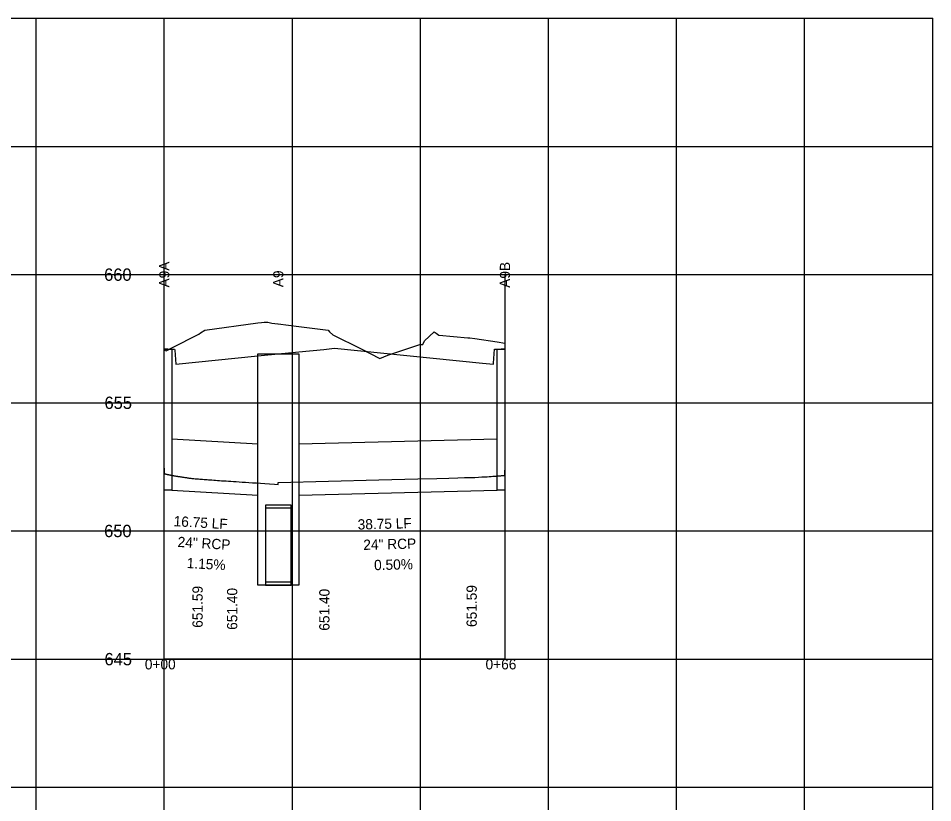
# Model space of a CAD drawing. Extents: x 2252703 to 2264864, y 13787568 to 13790989.
# Drawn here: x 2264585.2 to 2264763.7, y 13788457.8 to 13788610.8 of the extents above; entities that cross this region are included whole.
import ezdxf

# ---------------------------------------------------------------- set-up
doc = ezdxf.new("R2010")
doc.units = 0
for name, color, linetype in [('blank4', 7, 'Continuous'), ('BORD_grid_bottom_major_5int', 7, 'Continuous'), ('D_DRN_PROF_HGL', 7, 'Continuous'), ('D_PROF_1', 7, 'Continuous'), ('D_PROF_NOTES_1', 7, 'Continuous'), ('Default', 7, 'Continuous'), ('Drain_PipeInside', 7, 'Continuous'), ('E_Terrain', 7, 'Continuous'), ('Inlet', 7, 'Continuous'), ('z - Construction', 7, 'Continuous')]:
    doc.layers.add(name, color=color, linetype=linetype)

msp = doc.modelspace()

# ---------------------------------------------------------------- linework, layer by layer
at = {"layer": 'blank4'}
msp.add_lwpolyline([(2264613.67, 13788485.79), (2264613.67, 13788560.79), (2264680.17, 13788560.79), (2264680.17, 13788485.79)], close=True, dxfattribs=at)
at = {"layer": 'BORD_grid_bottom_major_5int'}
for p, q in [((2264413.67, 13788610.79), (2264763.67, 13788610.79)), ((2264588.67, 13788310.79), (2264588.67, 13788610.79)), ((2264613.67, 13788310.79), (2264613.67, 13788610.79)), ((2264638.67, 13788310.79), (2264638.67, 13788610.79)), ((2264663.67, 13788310.79), (2264663.67, 13788610.79)), ((2264688.67, 13788310.79), (2264688.67, 13788610.79)), ((2264713.67, 13788310.79), (2264713.67, 13788610.79)), ((2264738.67, 13788310.79), (2264738.67, 13788610.79)), ((2264763.67, 13788310.79), (2264763.67, 13788610.79)), ((2264413.67, 13788585.79), (2264763.67, 13788585.79)), ((2264413.67, 13788560.79), (2264763.67, 13788560.79)), ((2264413.67, 13788535.79), (2264763.67, 13788535.79)), ((2264413.67, 13788510.79), (2264763.67, 13788510.79)), ((2264413.67, 13788485.79), (2264763.67, 13788485.79)), ((2264413.67, 13788460.79), (2264763.67, 13788460.79))]:
    msp.add_line(p, q, dxfattribs=at)
at = {"layer": 'D_DRN_PROF_HGL'}
msp.add_line((2264635.92, 13788519.88), (2264635.92, 13788520.25), dxfattribs=at)
for points in [[(2264613.67, 13788523.07), (2264613.67, 13788522.05), (2264613.67, 13788522.05), (2264613.67, 13788522.04), (2264613.68, 13788522.04), (2264613.68, 13788522.03), (2264613.68, 13788522.03), (2264613.69, 13788522.02), (2264613.69, 13788522.02), (2264613.7, 13788522.01), (2264613.71, 13788522.01), (2264613.72, 13788522), (2264613.73, 13788521.99), (2264613.74, 13788521.99), (2264613.76, 13788521.98), (2264613.77, 13788521.97), (2264613.78, 13788521.97), (2264613.8, 13788521.96), (2264613.82, 13788521.95), (2264613.84, 13788521.95), (2264613.86, 13788521.94), (2264613.88, 13788521.93), (2264613.9, 13788521.92), (2264613.93, 13788521.92), (2264613.95, 13788521.91), (2264613.98, 13788521.9), (2264614.01, 13788521.89), (2264614.04, 13788521.88), (2264614.07, 13788521.87), (2264614.1, 13788521.87), (2264614.14, 13788521.86), (2264614.18, 13788521.85), (2264614.21, 13788521.84), (2264614.25, 13788521.83), (2264614.29, 13788521.82), (2264614.34, 13788521.81), (2264614.38, 13788521.8), (2264614.43, 13788521.79), (2264614.48, 13788521.78), (2264614.53, 13788521.77), (2264614.58, 13788521.76), (2264614.64, 13788521.74), (2264614.69, 13788521.73), (2264614.75, 13788521.72), (2264614.81, 13788521.71), (2264614.88, 13788521.7), (2264614.94, 13788521.68), (2264615.01, 13788521.67), (2264615.08, 13788521.66), (2264615.15, 13788521.65), (2264615.23, 13788521.63), (2264615.3, 13788521.62), (2264615.38, 13788521.6), (2264615.47, 13788521.59), (2264615.55, 13788521.57), (2264615.64, 13788521.56), (2264615.73, 13788521.54), (2264615.82, 13788521.53), (2264615.92, 13788521.51), (2264616.02, 13788521.5), (2264616.13, 13788521.48), (2264616.23, 13788521.46), (2264616.34, 13788521.44), (2264616.46, 13788521.43), (2264616.57, 13788521.41), (2264616.7, 13788521.39), (2264616.82, 13788521.37), (2264616.95, 13788521.35), (2264617.08, 13788521.33), (2264617.22, 13788521.31), (2264617.36, 13788521.29), (2264617.51, 13788521.27), (2264617.66, 13788521.24), (2264617.82, 13788521.22), (2264617.98, 13788521.2), (2264618.14, 13788521.17), (2264618.32, 13788521.15), (2264618.49, 13788521.12), (2264618.68, 13788521.1), (2264618.87, 13788521.07), (2264619.06, 13788521.04), (2264619.26, 13788521.02), (2264619.47, 13788521), (2264619.69, 13788520.98), (2264619.91, 13788520.97), (2264620.14, 13788520.95), (2264620.38, 13788520.93), (2264620.63, 13788520.91), (2264620.89, 13788520.89), (2264621.15, 13788520.87), (2264621.43, 13788520.85), (2264621.72, 13788520.83), (2264622.01, 13788520.81), (2264622.32, 13788520.78), (2264622.64, 13788520.76), (2264622.97, 13788520.74), (2264623.32, 13788520.71), (2264623.68, 13788520.69), (2264624.05, 13788520.66), (2264624.45, 13788520.63), (2264624.85, 13788520.6), (2264625.28, 13788520.57), (2264625.72, 13788520.54), (2264626.19, 13788520.51), (2264626.68, 13788520.48), (2264627.19, 13788520.44), (2264627.73, 13788520.41), (2264628.29, 13788520.37), (2264628.89, 13788520.33), (2264629.52, 13788520.29), (2264630.19, 13788520.25), (2264630.89, 13788520.2), (2264631.64, 13788520.15), (2264632.44, 13788520.1), (2264633.29, 13788520.05), (2264634.21, 13788519.99), (2264635.19, 13788519.93), (2264635.92, 13788519.88)], [(2264635.92, 13788520.25), (2264655.52, 13788520.75), (2264663.19, 13788520.94), (2264666.87, 13788521.04), (2264669.24, 13788521.1), (2264670.96, 13788521.15), (2264672.3, 13788521.19), (2264673.37, 13788521.22), (2264674.26, 13788521.25), (2264675.01, 13788521.28), (2264675.65, 13788521.32), (2264676.2, 13788521.35), (2264676.69, 13788521.38), (2264677.11, 13788521.41), (2264677.49, 13788521.43), (2264677.83, 13788521.45), (2264678.12, 13788521.47), (2264678.39, 13788521.49), (2264678.63, 13788521.51), (2264678.84, 13788521.52), (2264679.03, 13788521.54), (2264679.2, 13788521.55), (2264679.35, 13788521.56), (2264679.48, 13788521.58), (2264679.6, 13788521.59), (2264679.7, 13788521.6), (2264679.79, 13788521.61), (2264679.87, 13788521.62), (2264679.94, 13788521.62), (2264680, 13788521.63), (2264680.05, 13788521.64), (2264680.09, 13788521.65), (2264680.12, 13788521.65), (2264680.14, 13788521.66), (2264680.16, 13788521.66), (2264680.17, 13788521.67), (2264680.17, 13788521.68), (2264680.17, 13788522.63)]]:
    msp.add_lwpolyline(points, dxfattribs=at)
at = {"layer": 'D_PROF_1'}
msp.add_lwpolyline([(2264613.67, 13788546.39), (2264615.17, 13788546.24), (2264615.17, 13788546.24), (2264615.17, 13788546.24), (2264615.66, 13788546.24), (2264615.69, 13788546.24), (2264615.71, 13788546.04), (2264615.92, 13788543.33), (2264631.92, 13788544.93), (2264631.92, 13788544.93), (2264635.92, 13788545.33), (2264635.92, 13788545.33), (2264639.92, 13788545.73), (2264639.92, 13788545.73), (2264644.8, 13788546.21), (2264646.92, 13788546.43), (2264675.8, 13788543.54), (2264677.92, 13788543.33), (2264677.94, 13788543.52), (2264678.15, 13788546.24), (2264678.19, 13788546.24), (2264678.67, 13788546.24), (2264678.67, 13788546.24), (2264678.67, 13788546.24), (2264680.17, 13788546.39)], dxfattribs=at)
at = {"layer": 'Drain_PipeInside'}
for p, q in [((2264615.17, 13788528.74), (2264631.92, 13788527.78)), ((2264639.92, 13788527.77), (2264678.67, 13788528.74)), ((2264615.17, 13788518.74), (2264631.92, 13788517.78)), ((2264639.92, 13788517.77), (2264678.67, 13788518.74))]:
    msp.add_line(p, q, dxfattribs=at)
for points in [[(2264633.42, 13788500.84), (2264638.42, 13788500.84), (2264638.42, 13788515.84), (2264633.42, 13788515.84)], [(2264633.42, 13788500.24), (2264638.42, 13788500.24), (2264638.42, 13788515.24), (2264633.42, 13788515.24)]]:
    msp.add_lwpolyline(points, close=True, dxfattribs=at)
at = {"layer": 'E_Terrain'}
msp.add_lwpolyline([(2264613.67, 13788546.08), (2264613.69, 13788546.07), (2264614.02, 13788545.92), (2264615.17, 13788546.5), (2264615.17, 13788546.5), (2264620.44, 13788549.15), (2264620.77, 13788549.43), (2264621.56, 13788549.96), (2264621.6, 13788549.97), (2264631.92, 13788551.38), (2264631.92, 13788551.38), (2264632.64, 13788551.48), (2264633.16, 13788551.54), (2264633.85, 13788551.5), (2264633.88, 13788551.5), (2264634.66, 13788551.34), (2264635.86, 13788551.17), (2264635.92, 13788551.16), (2264635.92, 13788551.16), (2264639.92, 13788550.67), (2264639.92, 13788550.67), (2264645.67, 13788549.95), (2264645.94, 13788549.66), (2264646.55, 13788549.05), (2264652.09, 13788546.34), (2264655.72, 13788544.42), (2264657.32, 13788545.09), (2264663.58, 13788547.18), (2264664.13, 13788547.15), (2264664.49, 13788547.87), (2264666.34, 13788549.64), (2264666.52, 13788549.51), (2264666.75, 13788549.36), (2264667.28, 13788548.99), (2264667.34, 13788548.95), (2264672.91, 13788548.46), (2264672.99, 13788548.45), (2264673.29, 13788548.44), (2264674.31, 13788548.36), (2264678.67, 13788547.66), (2264678.67, 13788547.66), (2264680.17, 13788547.42)], dxfattribs=at)
at = {"layer": 'Inlet'}
for points in [[(2264613.67, 13788546.24), (2264615.17, 13788546.24), (2264615.17, 13788518.74), (2264613.67, 13788518.74)], [(2264631.92, 13788545.33), (2264639.92, 13788545.33), (2264639.92, 13788500.24), (2264631.92, 13788500.24)], [(2264678.67, 13788546.24), (2264680.17, 13788546.24), (2264680.17, 13788518.74), (2264678.67, 13788518.74)]]:
    msp.add_lwpolyline(points, close=True, dxfattribs=at)
at = {"layer": 'z - Construction'}
for p, q in [((2264613.67, 13788535.79), (2264680.17, 13788535.79)), ((2264613.67, 13788510.79), (2264680.17, 13788510.79))]:
    msp.add_line(p, q, dxfattribs=at)

# ---------------------------------------------------------------- texts
at = {"layer": 'D_PROF_NOTES_1'}
for s, rotation, p in [('A9A', 90, (2264614.67, 13788558.28)), ('A9B', 90, (2264681.17, 13788558.22)), ('A9', 90, (2264636.92, 13788558.33)), ('16.75 LF', 356.7198, (2264615.45, 13788511.73)), ('38.75 LF', 1.4321, (2264651.44, 13788511.06)), ('24" RCP', 356.7198, (2264616.23, 13788507.68)), ('24" RCP', 1.4321, (2264652.55, 13788507.09)), ('1.15%', 356.7198, (2264618.01, 13788503.57)), ('0.50%', 1.4321, (2264654.65, 13788503.14)), ('651.59', 90, (2264621.17, 13788491.9)), ('651.40', 90, (2264627.92, 13788491.5)), ('651.40', 90, (2264645.92, 13788491.33)), ('651.59', 90, (2264674.67, 13788492.06))]:
    msp.add_text(s, height=2, rotation=rotation, dxfattribs=at).set_placement(p)
at = {"layer": 'Default'}
for s, height, p in [('660', 2.4, (2264601.93, 13788559.59)), ('655', 2.4, (2264602, 13788534.59)), ('650', 2.4, (2264601.93, 13788509.59)), ('645', 2.4, (2264602, 13788484.59)), ('0+00', 2, (2264609.87, 13788483.79)), ('0+66', 2, (2264676.38, 13788483.79))]:
    msp.add_text(s, height=height, dxfattribs=at).set_placement(p)

doc.saveas('drawing.dxf')
